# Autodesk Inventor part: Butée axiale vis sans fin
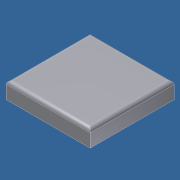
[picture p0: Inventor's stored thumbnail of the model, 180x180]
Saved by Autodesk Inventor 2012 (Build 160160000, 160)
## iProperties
Created: 2011-10
Part Number: Butée axiale vis sans fin
Material: Acier allié
Document SubType Name: Modeling
Designer: Laur
Mass: 0.204179 g
Surface Area: 0.7242 cm^2
Volume: 0.02601 cm^3
Density: 7.85 g/cm^3
Author: Laur
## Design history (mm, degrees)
sketch "Esquisse1"
  geometry: L1 (-2.55, 2.55)-(-2.55, -2.55) reference; L2 (-2.55, -2.55)-(2.55, -2.55) reference; L3 (2.55, -2.55)-(2.55, 2.55) reference; L4 (2.55, 2.55)-(-2.55, 2.55) reference; C1 r 1.98 at (0.022, -0.03) reference
extrude "épaisseur 1 mm" new body sketch "Esquisse1" distance "d0" = 1; taper "d1" = 0 deg
fillet "Congé 0,2" dims "d2" = 0.2
node "Solide1"
node "Corps solides"
node "Corps surfaciques"
node "Référence1"
